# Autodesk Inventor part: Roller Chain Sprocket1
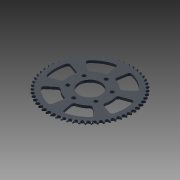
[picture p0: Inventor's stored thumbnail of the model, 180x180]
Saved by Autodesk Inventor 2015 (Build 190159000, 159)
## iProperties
Created: 2013-02
Part Number: Roller Chain Sprocket1
Material: Steel
Document SubType Name: Modeling
Designer: Marci
Density: 1 g/cm^3
Appearance: Dark Gray
CustomPartVersion: 1
Author: Marci
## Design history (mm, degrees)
sketch "Theoretical Tooth Profile"
  geometry: L1 (0, 0)-(0, 87.968); L2 (0, 0)-(9.511, 87.452); L3 (0, 87.968)-(9.511, 87.452); L4 (0, 87.968)-(4.108, 90.957); L5 (4.108, 90.957)-(-3.727, 88.259); L6 (-8.877, 87.487)-(-4.036, 89.154); L7 (-3.727, 88.259)-(-4.036, 89.154); L8 (4.036, 89.154)-(3.727, 88.259); L9 (0, 0)-(4.91, 90.564); A1 r 87.968 centre (0, 0) between (0, 87.968) and (9.511, 87.452); A2 r 90.697 centre (0, 0) between (4.789, 90.57) and (-4.789, 90.57); A3 r 3.207 centre (0, 87.968) between (-2.593, 86.082) and (2.593, 86.082); A4 r 5.12 centre (8.877, 87.487) between (4.789, 90.57) and (4.036, 89.154); A5 r 5.12 centre (-8.877, 87.487) between (-4.036, 89.154) and (-4.789, 90.57); A6 r 8.287 centre (4.108, 90.957) between (-3.727, 88.259) and (-2.593, 86.082); A7 r 8.287 centre (-4.108, 90.957) between (2.593, 86.082) and (3.727, 88.259); 2 further points
  constraints: 18 end point, 15 point on circle, 7 centre point, 3 coincident, 3 point on line, 3 symmetric about line, 3 tangent, 1 equal radius, 1 midpoint, 1 parallel, 1 vertical, 1 other
  dimensions: "d0" = 175.93631 diameter of A1 (computed from da_p, da_z); "d2" = 6.2069 deg angle of L2 L1 (computed from da_z); "d3" = 3.20675 radius of A3 (= 0.5 x da_Dr + da_SC); "d10" = 126.034 deg angle of L4 L1 (computed from da_z); "d11" = 17.0345 deg angle of L5 L4 (computed from da_z); "d12" = 5.08 distance of L3.start L4.end (= 0.8 x da_Dr); "d13" = 8.28675 distance of L4.end L5.end (= 1.3 x da_Dr + da_SC); "d14" = 8.89 distance of A4.centre L1.end (= 1.4 x da_Dr); "d23" = 2.8575 distance from line of L9.end L3 (= da_Ha)
sketch "Tooth Profile"
  geometry: L1 (0, 0)-(0, 87.968); L2 (0, 87.968)-(2.998, 86.831); L3 (0, 87.968)-(-2.998, 86.831); A1 r 3.207 centre (0, 87.968) between (-2.998, 86.831) and (2.998, 86.831); A2 r 45.72 centre (45.745, 70.613) between (4.615, 90.579) and (2.998, 86.831); A3 r 45.72 centre (-45.745, 70.613) between (-2.998, 86.831) and (-4.615, 90.579); A4 r 90.697 centre (0, 0) between (-4.615, 90.579) and (4.615, 90.579) reference; 1 further point
  constraints: 9 point on circle, 6 end point, 3 centre point, 2 tangent, 1 coincident, 1 equal radius, 1 vertical, 1 other
  dimensions: "d44" = 138.448 deg angle of L3 L2 (= da_Alfa); "d45" = 45.72 radius of A2 (= da_Re); "d46" = 3.20675 radius of A1 (= da_Ri)
sketch "Section Profile"
  geometry: L1 (90.697, 0)-(-90.697, 0) reference; L2 (79.363, 2.66)-(-79.363, 2.66); L3 (-79.363, 2.66)-(-79.363, -2.66); L4 (-79.363, -2.66)-(79.363, -2.66); L5 (79.363, -2.66)-(79.363, 2.66); L6 (79.363, 2.66)-(90.697, 2.66); L7 (90.697, 2.66)-(90.697, -2.66); L8 (90.697, -2.66)-(79.363, -2.66); L9 (79.363, -2.66)-(79.363, 2.66); L10 (86, 2.66)-(0, 2.66); L11 (0, 2.66)-(0, -2.66); L12 (0, -2.66)-(86, -2.66); L13 (0, 2.66)-(0, -2.66); L14 (90.697, 1.422)-(90.697, -1.422); A1 r 9.525 centre (86, -6.865) between (90.697, 1.422) and (86, 2.66); A2 r 9.525 centre (86, 6.865) between (86, -2.66) and (90.697, -1.422); 2 further points
  constraints: 26 end point, 7 midpoint, 5 perpendicular, 4 parallel, 4 point on circle, 3 point on line, 3 symmetric about line, 2 centre point, 2 horizontal, 2 tangent, 1 collinear, 1 other
  dimensions: "d30" = 5.3196 distance between parallel lines of L8 L6 (= da_Bf); "d31" = 158.72589 distance between parallel lines of L3 L5 (= da_Ds); "d32" = 5.3196 distance between parallel lines of L4 L2 (= da_Bs); "d33" = 1.23825 distance from line of L14.start L6 (= da_Ba); "d34" = 9.525 radius of A1 (= da_Rx); "d43" = 2.6598 distance between parallel lines of L4 L1 (computed from da_k, da_pt, da_Bs)
revolve "Shroud" stored, may be unused: angle "d36" = 90 deg
revolve "Strand" stored, may be unused: angle "d37" = 90 deg
pattern_linear "Strand Pattern" dims "d40" = 10.24 (= da_pt)
extrude "Theoretical Tooth" cut sketch "Theoretical Tooth Profile" stored distance "d18" = 10; taper "d19" = 0 deg; dims "d49" = 0, "form_type" = 0 [user parameter]
extrude "Tooth" cut sketch "Tooth Profile" stored distance "d47" = 10; taper "d48" = 0 deg; dims "d50" = 10, "form_type" = 0 [user parameter]
node "Timing Plane"
sketch "Sketch4"
  geometry: L1 (0, -87.968)-(75, -87.968); L2 (0, -87.968)-(75, -87.968); L3 (0, -87.968)-(75, -87.968); L4 (-38.11, -55.99)-(-53.486, -43.088); L5 (-8.639, -38.975)-(-12.124, -19.208); L6 (-46.749, -70.953)-(-65.61, -64.088); L7 (-46.749, -104.983)-(-65.61, -111.848); L8 (-38.11, -119.946)-(-53.486, -132.848); L9 (-8.639, -136.962)-(-12.124, -156.729); L10 (8.639, -136.962)-(12.124, -156.729); L11 (38.11, -119.946)-(53.486, -132.848); L12 (46.749, -104.983)-(65.61, -111.848); L13 (46.749, -70.953)-(65.61, -64.088); L14 (38.11, -55.99)-(53.486, -43.088); L15 (8.639, -38.975)-(12.124, -19.208); C1 r 23.5 at (0, -87.968); C2 r 4 at (0, -52.968); C3 r 4 at (-30.311, -70.468); C4 r 4 at (-30.311, -105.468); C5 r 4 at (0, -122.968); C6 r 4 at (30.311, -105.468); C7 r 4 at (30.311, -70.468); A1 r 86 centre (0, -87.968) between (6.806, -2.238) and (2.503, -2.004) reference; A2 r 45 centre (0, -87.968) between (-12.207, -44.655) and (-31.407, -55.741); A3 r 75 centre (0, -87.968) between (-18.266, -15.226) and (-53.863, -35.778); A4 r 5 centre (-50.272, -39.258) between (-53.863, -35.778) and (-53.486, -43.088); A5 r 5 centre (-17.048, -20.076) between (-12.124, -19.208) and (-18.266, -15.226); A6 r 5 centre (-13.563, -39.843) between (-12.207, -44.655) and (-8.639, -38.975); A7 r 5 centre (-34.896, -52.16) between (-38.11, -55.99) and (-31.407, -55.741); A8 r 75 centre (0, -87.968) between (-72.129, -67.416) and (-72.129, -108.52); A9 r 5 centre (-67.321, -68.786) between (-65.61, -64.088) and (-72.129, -67.416); A10 r 5 centre (-67.321, -107.15) between (-72.129, -108.52) and (-65.61, -111.848); A11 r 5 centre (-48.459, -75.651) between (-43.613, -76.883) and (-46.749, -70.953); A12 r 5 centre (-48.459, -100.285) between (-46.749, -104.983) and (-43.613, -99.053); A13 r 45 centre (0, -87.968) between (-43.613, -76.883) and (-43.613, -99.053); A14 r 75 centre (0, -87.968) between (-53.863, -140.158) and (-18.266, -160.71); A15 r 5 centre (-50.272, -136.679) between (-53.486, -132.848) and (-53.863, -140.158); A16 r 5 centre (-17.048, -155.86) between (-18.266, -160.71) and (-12.124, -156.729); A17 r 5 centre (-34.896, -123.777) between (-31.407, -120.196) and (-38.11, -119.946); A18 r 5 centre (-13.563, -136.093) between (-8.639, -136.962) and (-12.207, -131.281); A19 r 45 centre (0, -87.968) between (-31.407, -120.196) and (-12.207, -131.281); A20 r 75 centre (0, -87.968) between (18.266, -160.71) and (53.863, -140.158); A21 r 5 centre (17.048, -155.86) between (12.124, -156.729) and (18.266, -160.71); A22 r 5 centre (50.272, -136.679) between (53.863, -140.158) and (53.486, -132.848); A23 r 5 centre (13.563, -136.093) between (12.207, -131.281) and (8.639, -136.962); A24 r 5 centre (34.896, -123.777) between (38.11, -119.946) and (31.407, -120.196); A25 r 45 centre (0, -87.968) between (12.207, -131.281) and (31.407, -120.196); A26 r 75 centre (0, -87.968) between (72.129, -108.52) and (72.129, -67.416); A27 r 5 centre (67.321, -107.15) between (65.61, -111.848) and (72.129, -108.52); A28 r 5 centre (67.321, -68.786) between (72.129, -67.416) and (65.61, -64.088); A29 r 5 centre (48.459, -100.285) between (43.613, -99.053) and (46.749, -104.983); A30 r 5 centre (48.459, -75.651) between (46.749, -70.953) and (43.613, -76.883); A31 r 45 centre (0, -87.968) between (43.613, -99.053) and (43.613, -76.883); A32 r 75 centre (0, -87.968) between (53.863, -35.778) and (18.266, -15.226); A33 r 5 centre (50.272, -39.258) between (53.486, -43.088) and (53.863, -35.778); A34 r 5 centre (17.048, -20.076) between (18.266, -15.226) and (12.124, -19.208); A35 r 5 centre (34.896, -52.16) between (31.407, -55.741) and (38.11, -55.99); A36 r 5 centre (13.563, -39.843) between (8.639, -38.975) and (12.207, -44.655); A37 r 45 centre (0, -87.968) between (31.407, -55.741) and (12.207, -44.655); 14 further points
  constraints: 86 point on circle, 43 centre point, 30 end point, 14 point on line, 8 tangent, 7 coincident, 3 equal radius, 3 horizontal, 158 other
  dimensions: "d55" = 8 diameter of C2; "d58" = 360 deg dimension on C1.centre C2.centre (derived); "d61" = 150 diameter of A3; "d65" = 5 radius of A4; "d68" = 360 deg dimension on A1.centre L5.start (derived)
extrude "Extrusion4" cut sketch "Sketch4" distance "d70" = 50; taper "d71" = 0 deg
body "Solid1"
pattern_circular "Tooth Pattern" dims angle "d21" = 360 deg
other parameters: "da_p" = 9.525 [user parameter; used in 1 equation term], "da_Dr" = 6.35 [user parameter; used in 4 equation terms], "da_SC" = 0.03175 [user parameter; used in 2 equation terms], "da_Ha" = 2.8575 [user parameter; used in 1 equation term], "da_pt" = 10.24 [user parameter; used in 2 equation terms], "da_Bf" = 5.3196 [user parameter; used in 1 equation term], "d28" = 0, "d29" = 0, "da_Ba" = 1.23825 [user parameter; used in 1 equation term], "da_Rx" = 9.525 [user parameter; used in 1 equation term], "da_Ra" = 0.381 [user parameter], "da_Bs" = 5.3196 [user parameter; used in 2 equation terms], "da_Ds" = 158.72589 [user parameter; used in 1 equation term], "d42" = 0, "da_Re" = 45.72 [user parameter; used in 1 equation term], "da_Ri" = 3.20675 [user parameter; used in 1 equation term], "da_Alfa" = 138.448 deg [user parameter; used in 1 equation term], "d62" = 120 deg, "d63" = 100 deg, "d64" = 140 deg
